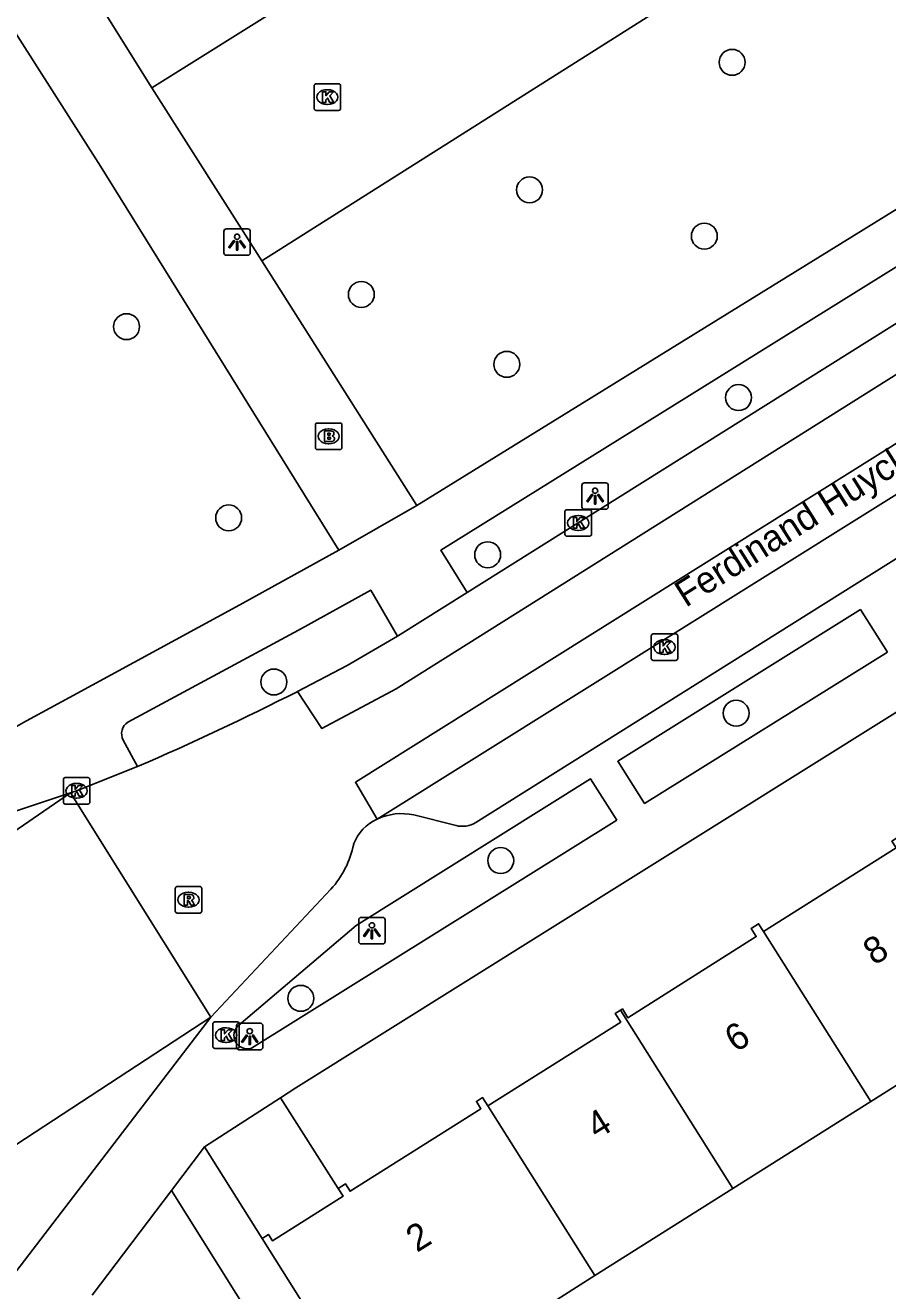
# Model space of a CAD drawing. Extents: x 160077 to 160945, y 386481 to 387498.
# Drawn here: x 160409.7 to 160442.23, y 386860.35 to 386908.06 of the extents above; entities that cross this region are included whole.
import ezdxf

# ---------------------------------------------------------------- set-up
doc = ezdxf.new("R2010")
doc.units = 0
for name, color, linetype in [('IMGEO_Boom', 7, 'Continuous'), ('IMGEO_Brandkraan', 7, 'Continuous'), ('IMGEO_Fietspad_gesloten', 7, 'Continuous'), ('IMGEO_Groenvoorziening', 7, 'Continuous'), ('IMGEO_Kolk', 7, 'Continuous'), ('IMGEO_Lichtpunt', 7, 'Continuous'), ('IMGEO_Openbare_ruimte_label', 7, 'Continuous'), ('IMGEO_Pand', 7, 'Continuous'), ('IMGEO_Pand_nummerreeks', 7, 'Continuous'), ('IMGEO_Rijbaan_lokaal_gesloten', 7, 'Continuous'), ('IMGEO_Rijbaan_lokaal_open', 7, 'Continuous'), ('IMGEO_Rioolput', 7, 'Continuous'), ('IMGEO_Voetpad_open', 7, 'Continuous')]:
    doc.layers.add(name, color=color, linetype=linetype)

msp = doc.modelspace()

# ---------------------------------------------------------------- linework, layer by layer
at = {"layer": 'IMGEO_Boom'}
for centre in [(160436.359, 386906.663), (160428.721, 386901.854), (160435.311, 386900.11), (160422.376, 386897.911), (160413.525, 386896.698), (160427.863, 386895.276), (160436.602, 386894.023), (160417.375, 386889.487), (160427.141, 386888.098), (160419.081, 386883.301), (160436.512, 386882.124), (160427.633, 386876.567), (160420.093, 386871.374)]:
    msp.add_circle(centre, 0.489, dxfattribs=at)
at = {"layer": 'IMGEO_Brandkraan'}
for p, q in [((160420.644, 386892.138), (160420.644, 386892.99)), ((160420.719, 386893.064), (160421.571, 386893.064)), ((160421.132, 386892.844), (160421.157, 386892.844)), ((160421.645, 386892.99), (160421.645, 386892.138)), ((160421.571, 386892.064), (160420.719, 386892.064)), ((160421.155, 386892.284), (160421.13, 386892.284))]:
    msp.add_line(p, q, dxfattribs=at)
for points in [[(160420.644, 386892.138), (160420.644, 386892.99)], [(160420.719, 386893.064), (160421.571, 386893.064)], [(160421.645, 386892.99), (160421.645, 386892.138)], [(160420.992, 386892.764), (160420.992, 386892.364), (160421.205, 386892.364)], [(160421.223, 386892.764), (160420.992, 386892.764)], [(160421.171, 386892.683), (160421.117, 386892.683), (160421.117, 386892.607)], [(160421.117, 386892.607), (160421.17, 386892.607)], [(160421.179, 386892.531), (160421.117, 386892.531), (160421.117, 386892.45)], [(160421.117, 386892.45), (160421.179, 386892.45)], [(160421.571, 386892.064), (160420.719, 386892.064)]]:
    msp.add_lwpolyline(points, dxfattribs=at)
for centre, radius, start, end in [((160420.721, 386892.988), 0.0765, 91.552, 178.448), ((160420.721, 386892.988), 0.0765, 91.552, 178.448), ((160421.569, 386892.988), 0.0765, 1.552, 88.448), ((160421.569, 386892.988), 0.0765, 1.552, 88.448), ((160421.172, 386892.645), 0.0379, 267.8285, 90.9355), ((160421.18, 386892.49), 0.0404, 269.8759, 90.5077), ((160421.211, 386892.615), 0.251, 268.6676, 293.5347), ((160421.227, 386892.619), 0.145, 59.4692, 91.5367), ((160421.252, 386892.666), 0.0922, 285.5137, 58.1501), ((160421.257, 386892.474), 0.105, 301.3115, 78.989), ((160420.721, 386892.14), 0.0765, 181.552, 268.448), ((160420.721, 386892.14), 0.0765, 181.552, 268.448), ((160421.569, 386892.14), 0.0765, 271.552, 358.448), ((160421.569, 386892.14), 0.0765, 271.552, 358.448)]:
    msp.add_arc(centre, radius, start, end, dxfattribs=at)
for centre, major_axis, ratio, start_param, end_param in [((160421.131, 386892.564), (-0.387, 0.002), 0.722429, 4.712389, 7.853982), ((160421.156, 386892.564), (-0.39, 0.002), 0.717154, 1.570796, 4.712389)]:
    msp.add_ellipse(centre, major_axis=major_axis, ratio=ratio, start_param=start_param, end_param=end_param, dxfattribs=at)
at = {"layer": 'IMGEO_Fietspad_gesloten'}
for points in [[(160408.572, 386878.179), (160411.413, 386879.123)], [(160416.702, 386870.665), (160416.575, 386870.496), (160409.222, 386860.905), (160408.542, 386860.066), (160407.918, 386859.274), (160407.31, 386858.499), (160403.74, 386853.668)]]:
    msp.add_lwpolyline(points, dxfattribs=at)
at = {"layer": 'IMGEO_Groenvoorziening'}
msp.add_lwpolyline([(160419.331, 386867.627), (160421.508, 386864.204)], dxfattribs=at)
at = {"layer": 'IMGEO_Kolk'}
for p, q in [((160420.595, 386904.926), (160420.595, 386905.778)), ((160420.67, 386905.852), (160421.522, 386905.852)), ((160421.596, 386905.778), (160421.596, 386904.926)), ((160421.083, 386905.632), (160421.108, 386905.632)), ((160421.522, 386904.852), (160420.67, 386904.852)), ((160421.106, 386905.072), (160421.081, 386905.072)), ((160430.056, 386888.871), (160430.056, 386889.723)), ((160430.131, 386889.797), (160430.983, 386889.797)), ((160430.544, 386889.577), (160430.569, 386889.577)), ((160431.057, 386889.723), (160431.057, 386888.871)), ((160430.567, 386889.017), (160430.542, 386889.017)), ((160430.983, 386888.797), (160430.131, 386888.797)), ((160433.311, 386884.189), (160433.311, 386885.041)), ((160433.386, 386885.115), (160434.238, 386885.115)), ((160433.799, 386884.895), (160433.824, 386884.895)), ((160434.312, 386885.041), (160434.312, 386884.189)), ((160433.822, 386884.335), (160433.797, 386884.335)), ((160434.238, 386884.115), (160433.386, 386884.115)), ((160411.139, 386878.773), (160411.139, 386879.625)), ((160411.214, 386879.699), (160412.066, 386879.699)), ((160411.627, 386879.479), (160411.652, 386879.479)), ((160412.14, 386879.625), (160412.14, 386878.773)), ((160412.066, 386878.699), (160411.214, 386878.699)), ((160411.65, 386878.919), (160411.625, 386878.919)), ((160416.775, 386869.56), (160416.775, 386870.412)), ((160416.85, 386870.486), (160417.702, 386870.486)), ((160417.776, 386870.412), (160417.776, 386869.56)), ((160417.263, 386870.266), (160417.288, 386870.266)), ((160417.702, 386869.486), (160416.85, 386869.486)), ((160417.286, 386869.706), (160417.261, 386869.706))]:
    msp.add_line(p, q, dxfattribs=at)
for points in [[(160420.595, 386904.926), (160420.595, 386905.778)], [(160420.67, 386905.852), (160421.522, 386905.852)], [(160421.596, 386905.778), (160421.596, 386904.926)], [(160420.916, 386905.552), (160421.039, 386905.552), (160421.039, 386905.401), (160421.169, 386905.552), (160421.333, 386905.552), (160421.187, 386905.401), (160421.34, 386905.152), (160421.188, 386905.152), (160421.103, 386905.316), (160421.039, 386905.249), (160421.039, 386905.152), (160420.916, 386905.152), (160420.916, 386905.552)], [(160421.522, 386904.852), (160420.67, 386904.852)], [(160430.056, 386888.871), (160430.056, 386889.723)], [(160430.131, 386889.797), (160430.983, 386889.797)], [(160430.377, 386889.497), (160430.5, 386889.497), (160430.5, 386889.346), (160430.63, 386889.497), (160430.794, 386889.497), (160430.648, 386889.346), (160430.801, 386889.097), (160430.649, 386889.097), (160430.564, 386889.261), (160430.5, 386889.194), (160430.5, 386889.097), (160430.377, 386889.097), (160430.377, 386889.497)], [(160431.057, 386889.723), (160431.057, 386888.871)], [(160430.983, 386888.797), (160430.131, 386888.797)], [(160433.311, 386884.189), (160433.311, 386885.041)], [(160433.386, 386885.115), (160434.238, 386885.115)], [(160433.632, 386884.815), (160433.755, 386884.815), (160433.755, 386884.664), (160433.885, 386884.815), (160434.049, 386884.815), (160433.903, 386884.664), (160434.056, 386884.415), (160433.904, 386884.415), (160433.819, 386884.579), (160433.755, 386884.512), (160433.755, 386884.415), (160433.632, 386884.415), (160433.632, 386884.815)], [(160434.312, 386885.041), (160434.312, 386884.189)], [(160434.238, 386884.115), (160433.386, 386884.115)], [(160411.139, 386878.773), (160411.139, 386879.625)], [(160411.214, 386879.699), (160412.066, 386879.699)], [(160412.14, 386879.625), (160412.14, 386878.773)], [(160411.46, 386879.399), (160411.583, 386879.399), (160411.583, 386879.248), (160411.713, 386879.399), (160411.877, 386879.399), (160411.731, 386879.248), (160411.884, 386878.999), (160411.732, 386878.999), (160411.647, 386879.163), (160411.583, 386879.096), (160411.583, 386878.999), (160411.46, 386878.999), (160411.46, 386879.399)], [(160412.066, 386878.699), (160411.214, 386878.699)], [(160416.775, 386869.56), (160416.775, 386870.412)], [(160416.85, 386870.486), (160417.702, 386870.486)], [(160417.776, 386870.412), (160417.776, 386869.56)], [(160417.096, 386870.186), (160417.219, 386870.186), (160417.219, 386870.035), (160417.349, 386870.186), (160417.513, 386870.186), (160417.367, 386870.035), (160417.52, 386869.786), (160417.368, 386869.786), (160417.283, 386869.95), (160417.219, 386869.883), (160417.219, 386869.786), (160417.096, 386869.786), (160417.096, 386870.186)], [(160417.702, 386869.486), (160416.85, 386869.486)]]:
    msp.add_lwpolyline(points, dxfattribs=at)
for centre, start, end in [((160420.672, 386905.776), 91.552, 178.448), ((160420.672, 386905.776), 91.552, 178.448), ((160421.52, 386905.776), 1.552, 88.448), ((160421.52, 386905.776), 1.552, 88.448), ((160420.672, 386904.928), 181.552, 268.448), ((160420.672, 386904.928), 181.552, 268.448), ((160421.52, 386904.928), 271.552, 358.448), ((160421.52, 386904.928), 271.552, 358.448), ((160430.133, 386889.721), 91.552, 178.448), ((160430.133, 386889.721), 91.552, 178.448), ((160430.981, 386889.721), 1.552, 88.448), ((160430.981, 386889.721), 1.552, 88.448), ((160430.133, 386888.873), 181.552, 268.448), ((160430.133, 386888.873), 181.552, 268.448), ((160430.981, 386888.873), 271.552, 358.448), ((160430.981, 386888.873), 271.552, 358.448), ((160433.388, 386885.039), 91.552, 178.448), ((160433.388, 386885.039), 91.552, 178.448), ((160434.236, 386885.039), 1.552, 88.448), ((160434.236, 386885.039), 1.552, 88.448), ((160433.388, 386884.191), 181.552, 268.448), ((160433.388, 386884.191), 181.552, 268.448), ((160434.236, 386884.191), 271.552, 358.448), ((160434.236, 386884.191), 271.552, 358.448), ((160411.216, 386879.623), 91.552, 178.448), ((160411.216, 386879.623), 91.552, 178.448), ((160412.064, 386879.623), 1.552, 88.448), ((160412.064, 386879.623), 1.552, 88.448), ((160411.216, 386878.775), 181.552, 268.448), ((160411.216, 386878.775), 181.552, 268.448), ((160412.064, 386878.775), 271.552, 358.448), ((160412.064, 386878.775), 271.552, 358.448), ((160416.852, 386870.41), 91.552, 178.448), ((160416.852, 386870.41), 91.552, 178.448), ((160417.7, 386870.41), 1.552, 88.448), ((160417.7, 386870.41), 1.552, 88.448), ((160416.852, 386869.562), 181.552, 268.448), ((160416.852, 386869.562), 181.552, 268.448), ((160417.7, 386869.562), 271.552, 358.448), ((160417.7, 386869.562), 271.552, 358.448)]:
    msp.add_arc(centre, 0.0765, start, end, dxfattribs=at)
for centre, major_axis, ratio, start_param, end_param in [((160421.082, 386905.352), (-0.387, 0.002), 0.722429, 4.712389, 7.853982), ((160421.107, 386905.352), (-0.39, 0.002), 0.717154, 1.570796, 4.712389), ((160430.543, 386889.297), (-0.387, 0.002), 0.722429, 4.712389, 7.853982), ((160430.568, 386889.297), (-0.39, 0.002), 0.717154, 1.570796, 4.712389), ((160433.798, 386884.615), (-0.387, 0.002), 0.722429, 4.712389, 7.853982), ((160433.823, 386884.615), (-0.39, 0.002), 0.717154, 1.570796, 4.712389), ((160411.626, 386879.199), (-0.387, 0.002), 0.722429, 4.712389, 7.853982), ((160411.651, 386879.199), (-0.39, 0.002), 0.717154, 1.570796, 4.712389), ((160417.262, 386869.986), (-0.387, 0.002), 0.722429, 4.712389, 7.853982), ((160417.287, 386869.986), (-0.39, 0.002), 0.717154, 1.570796, 4.712389)]:
    msp.add_ellipse(centre, major_axis=major_axis, ratio=ratio, start_param=start_param, end_param=end_param, dxfattribs=at)
at = {"layer": 'IMGEO_Lichtpunt'}
for p, q in [((160417.193, 386900.289), (160417.193, 386899.482)), ((160417.193, 386900.289), (160417.193, 386899.482)), ((160418.095, 386900.384), (160417.287, 386900.384)), ((160418.095, 386900.384), (160417.287, 386900.384)), ((160418.189, 386899.482), (160418.189, 386900.289)), ((160418.189, 386899.482), (160418.189, 386900.289)), ((160417.287, 386899.388), (160418.095, 386899.388)), ((160417.287, 386899.388), (160418.095, 386899.388)), ((160430.695, 386890.715), (160430.695, 386889.908)), ((160430.695, 386890.715), (160430.695, 386889.908)), ((160431.597, 386890.81), (160430.789, 386890.81)), ((160431.597, 386890.81), (160430.789, 386890.81)), ((160431.691, 386889.908), (160431.691, 386890.715)), ((160431.691, 386889.908), (160431.691, 386890.715)), ((160430.789, 386889.814), (160431.597, 386889.814)), ((160430.789, 386889.814), (160431.597, 386889.814)), ((160422.278, 386874.329), (160422.278, 386873.522)), ((160422.278, 386874.329), (160422.278, 386873.522)), ((160423.18, 386874.424), (160422.372, 386874.424)), ((160423.18, 386874.424), (160422.372, 386874.424)), ((160423.274, 386873.522), (160423.274, 386874.329)), ((160423.274, 386873.522), (160423.274, 386874.329)), ((160422.372, 386873.428), (160423.18, 386873.428)), ((160422.372, 386873.428), (160423.18, 386873.428)), ((160418.571, 386870.433), (160417.763, 386870.433)), ((160418.571, 386870.433), (160417.763, 386870.433)), ((160417.669, 386870.338), (160417.669, 386869.531)), ((160417.669, 386870.338), (160417.669, 386869.531)), ((160418.665, 386869.531), (160418.665, 386870.338)), ((160418.665, 386869.531), (160418.665, 386870.338)), ((160417.763, 386869.437), (160418.571, 386869.437)), ((160417.763, 386869.437), (160418.571, 386869.437))]:
    msp.add_line(p, q, dxfattribs=at)
for points in [[(160417.567, 386899.953), (160417.606, 386899.925), (160417.418, 386899.663), (160417.38, 386899.69), (160417.567, 386899.953)], [(160417.669, 386899.905), (160417.716, 386899.905), (160417.716, 386899.583), (160417.669, 386899.583), (160417.669, 386899.905)], [(160417.779, 386899.925), (160417.817, 386899.952), (160418.004, 386899.69), (160417.965, 386899.662), (160417.779, 386899.925)], [(160431.069, 386890.379), (160431.108, 386890.351), (160430.92, 386890.089), (160430.882, 386890.116), (160431.069, 386890.379)], [(160431.171, 386890.331), (160431.218, 386890.331), (160431.218, 386890.009), (160431.171, 386890.009), (160431.171, 386890.331)], [(160431.281, 386890.351), (160431.319, 386890.378), (160431.506, 386890.116), (160431.467, 386890.088), (160431.281, 386890.351)], [(160422.652, 386873.993), (160422.691, 386873.965), (160422.503, 386873.703), (160422.465, 386873.73), (160422.652, 386873.993)], [(160422.754, 386873.945), (160422.801, 386873.945), (160422.801, 386873.623), (160422.754, 386873.623), (160422.754, 386873.945)], [(160422.864, 386873.965), (160422.902, 386873.992), (160423.089, 386873.73), (160423.05, 386873.702), (160422.864, 386873.965)], [(160418.043, 386870.002), (160418.082, 386869.974), (160417.894, 386869.712), (160417.856, 386869.739), (160418.043, 386870.002)], [(160418.145, 386869.954), (160418.192, 386869.954), (160418.192, 386869.632), (160418.145, 386869.632), (160418.145, 386869.954)], [(160418.255, 386869.974), (160418.293, 386870.001), (160418.48, 386869.739), (160418.441, 386869.711), (160418.255, 386869.974)]]:
    msp.add_lwpolyline(points, dxfattribs=at)
for centre in [(160417.692, 386900.087), (160431.194, 386890.513), (160422.777, 386874.127), (160418.168, 386870.136)]:
    msp.add_circle(centre, 0.0994, dxfattribs=at)
for centre, start, end in [((160417.287, 386900.289), 90, 180), ((160417.287, 386900.289), 90, 180), ((160418.095, 386900.289), 0, 90), ((160418.095, 386900.289), 0, 90), ((160417.287, 386899.482), 180, 270), ((160417.287, 386899.482), 180, 270), ((160418.095, 386899.482), 270, 0), ((160418.095, 386899.482), 270, 360), ((160430.789, 386890.715), 90, 180), ((160430.789, 386890.715), 90, 180), ((160431.597, 386890.715), 0, 90), ((160431.597, 386890.715), 0, 90), ((160430.789, 386889.908), 180, 270), ((160430.789, 386889.908), 180, 270), ((160431.597, 386889.908), 270, 0), ((160431.597, 386889.908), 270, 360), ((160422.372, 386874.329), 90, 180), ((160422.372, 386874.329), 90, 180), ((160423.18, 386874.329), 0, 90), ((160423.18, 386874.329), 0, 90), ((160422.372, 386873.522), 180, 270), ((160422.372, 386873.522), 180, 270), ((160423.18, 386873.522), 270, 0), ((160423.18, 386873.522), 270, 360), ((160417.763, 386870.338), 90, 180), ((160417.763, 386870.338), 90, 180), ((160418.571, 386870.338), 0, 90), ((160418.571, 386870.338), 0, 90), ((160417.763, 386869.531), 180, 270), ((160417.763, 386869.531), 180, 270), ((160418.571, 386869.531), 270, 0), ((160418.571, 386869.531), 270, 360)]:
    msp.add_arc(centre, 0.0946, start, end, dxfattribs=at)
at = {"layer": 'IMGEO_Pand'}
for points in [[(160437.543, 386873.893), (160442.548, 386877.05), (160442.388, 386877.304), (160442.592, 386877.433)], [(160432.147, 386870.927), (160432.223, 386870.974), (160432.43, 386870.642), (160437.271, 386873.702), (160437.08, 386874.008), (160437.359, 386874.184), (160437.543, 386873.893)], [(160437.543, 386873.893), (160441.594, 386867.488)], [(160427.149, 386867.317), (160432.16, 386870.477), (160431.953, 386870.806), (160432.147, 386870.927)], [(160436.391, 386864.204), (160432.147, 386870.927)], [(160446.465, 386870.563), (160441.594, 386867.488)], [(160421.508, 386864.204), (160421.78, 386864.376), (160421.953, 386864.101), (160426.888, 386867.213), (160426.715, 386867.487), (160426.949, 386867.634), (160427.149, 386867.317)], [(160431.189, 386860.92), (160427.149, 386867.317)], [(160441.594, 386867.488), (160436.391, 386864.204)], [(160421.508, 386864.204), (160421.69, 386863.915), (160419.026, 386862.235), (160418.875, 386862.476), (160418.632, 386862.323)], [(160436.391, 386864.204), (160431.189, 386860.92)], [(160422.839, 386855.651), (160418.632, 386862.323)], [(160431.189, 386860.92), (160429.346, 386859.754), (160427.069, 386858.318), (160422.839, 386855.651)]]:
    msp.add_lwpolyline(points, dxfattribs=at)
at = {"layer": 'IMGEO_Rijbaan_lokaal_gesloten'}
for points in [[(160419.976, 386882.948), (160420.887, 386881.55), (160423.695, 386883.049), (160454.149, 386902.178), (160498.016, 386929.634)], [(160499.173, 386927.789), (160470.277, 386909.673), (160422.153, 386879.524), (160422.979, 386878.128)], [(160498.541, 386925.423), (160471.132, 386908.242), (160422.979, 386878.128)], [(160453.275, 386903.561), (160447.876, 386900.154), (160430.557, 386889.297), (160426.372, 386886.679)], [(160423.735, 386885.033), (160426.372, 386886.679)], [(160419.976, 386882.948), (160421.837, 386883.922), (160423.735, 386885.033)], [(160399.68, 386871.062), (160411.413, 386879.123)], [(160416.702, 386870.665), (160411.413, 386879.123)], [(160404.134, 386862.447), (160416.702, 386870.665)]]:
    msp.add_lwpolyline(points, dxfattribs=at)
at = {"layer": 'IMGEO_Rijbaan_lokaal_open'}
for points in [[(160418.626, 386899.176), (160445.701, 386916.313)], [(160416.321, 386914.248), (160419.644, 386908.926), (160414.476, 386905.699)], [(160414.476, 386905.699), (160418.626, 386899.176)], [(160411.413, 386879.123), (160411.64, 386879.199), (160413.94, 386880.112)], [(160416.702, 386870.665), (160421.228, 386875.484)]]:
    msp.add_lwpolyline(points, dxfattribs=at)
for centre, radius, start, end in [((160369.624, 386982.274), 111.36, 293.45046, 296.88228), ((160423.627, 386876.624), 1.638, 113.3148, 159.994), ((160418.55, 386877.906), 3.611, 317.8708, 348.4611)]:
    msp.add_arc(centre, radius, start, end, dxfattribs=at)
at = {"layer": 'IMGEO_Rioolput'}
for p, q in [((160415.36, 386874.665), (160415.36, 386875.517)), ((160415.435, 386875.591), (160416.287, 386875.591)), ((160415.848, 386875.371), (160415.873, 386875.371)), ((160416.361, 386875.517), (160416.361, 386874.665)), ((160415.871, 386874.811), (160415.846, 386874.811)), ((160416.287, 386874.591), (160415.435, 386874.591))]:
    msp.add_line(p, q, dxfattribs=at)
for points in [[(160415.36, 386874.665), (160415.36, 386875.517)], [(160415.435, 386875.591), (160416.287, 386875.591)], [(160415.949, 386875.289), (160415.697, 386875.291), (160415.697, 386874.891)], [(160415.875, 386875.21), (160415.821, 386875.21), (160415.821, 386875.129)], [(160416.361, 386875.517), (160416.361, 386874.665)], [(160415.697, 386874.891), (160415.821, 386874.891), (160415.821, 386875.053), (160415.832, 386875.053)], [(160415.821, 386875.129), (160415.873, 386875.129)], [(160415.879, 386875.024), (160415.95, 386874.891), (160416.09, 386874.891), (160416.025, 386875.017)], [(160416.287, 386874.591), (160415.435, 386874.591)]]:
    msp.add_lwpolyline(points, dxfattribs=at)
for centre, radius, start, end in [((160415.437, 386875.515), 0.0765, 91.552, 178.448), ((160415.437, 386875.515), 0.0765, 91.552, 178.448), ((160415.881, 386875.114), 0.0964, 77.0061, 93.1865), ((160415.895, 386875.171), 0.0378, 276.6634, 79.6772), ((160415.948, 386875.179), 0.109, 350.3612, 89.416), ((160415.946, 386875.179), 0.112, 277.5842, 350.9817), ((160416.285, 386875.515), 0.0765, 1.552, 88.448), ((160416.285, 386875.515), 0.0765, 1.552, 88.448), ((160415.831, 386875), 0.0533, 26.0293, 88.6989), ((160415.857, 386875.318), 0.19, 274.7715, 282.9687), ((160415.93, 386874.964), 0.108, 29.5134, 73.7905), ((160415.437, 386874.667), 0.0765, 181.552, 268.448), ((160415.437, 386874.667), 0.0765, 181.552, 268.448), ((160416.285, 386874.667), 0.0765, 271.552, 358.448), ((160416.285, 386874.667), 0.0765, 271.552, 358.448)]:
    msp.add_arc(centre, radius, start, end, dxfattribs=at)
for centre, major_axis, ratio, start_param, end_param in [((160415.847, 386875.091), (-0.387, 0.002), 0.722429, 4.712389, 7.853982), ((160415.872, 386875.091), (-0.39, 0.002), 0.717154, 1.570796, 4.712389)]:
    msp.add_ellipse(centre, major_axis=major_axis, ratio=ratio, start_param=start_param, end_param=end_param, dxfattribs=at)
at = {"layer": 'IMGEO_Voetpad_open'}
for points in [[(160387.823, 386942.091), (160389.939, 386938.794), (160392.284, 386934.918), (160394.729, 386930.878), (160396.796, 386927.687), (160399.533, 386923.281), (160403.038, 386917.636), (160408.864, 386908.506), (160412.535, 386902.752), (160416.406, 386896.516), (160421.525, 386888.269)], [(160426.691, 386878.004), (160472.2, 386906.553), (160496.977, 386922.083)], [(160503.979, 386920.59), (160500, 386918.098), (160419.904, 386867.997), (160419.331, 386867.627)], [(160414.476, 386905.699), (160411.153, 386911.02)], [(160450.017, 386905.729), (160424.466, 386889.949)], [(160426.372, 386886.679), (160425.369, 386888.267), (160452.383, 386905.061), (160453.275, 386903.561)], [(160424.466, 386889.949), (160418.626, 386899.176)], [(160424.466, 386889.949), (160421.525, 386888.269)], [(160421.525, 386888.269), (160417.798, 386886.204), (160411.377, 386882.716), (160409.893, 386881.917)], [(160413.576, 386881.791), (160420.003, 386885.249), (160422.733, 386886.769), (160423.735, 386885.033)], [(160442.215, 386884.428), (160441.198, 386886.032), (160432.048, 386880.31), (160433.056, 386878.721), (160442.215, 386884.428)], [(160413.94, 386880.112), (160413.4, 386881.105)], [(160432.012, 386878.087), (160431.019, 386879.651), (160422.186, 386874.126), (160417.76, 386870.362)], [(160418.233, 386869.493), (160432.012, 386878.087)], [(160424.352, 386878.287), (160425.949, 386877.889)], [(160416.466, 386865.776), (160419.331, 386867.627)], [(160416.466, 386865.776), (160415.215, 386864.126)], [(160418.632, 386862.323), (160416.466, 386865.776)], [(160415.215, 386864.126), (160412.23, 386860.189)], [(160423.252, 386842.489), (160427.229, 386844.983), (160415.215, 386864.126)]]:
    msp.add_lwpolyline(points, dxfattribs=at)
for centre, radius, start, end in [((160400.977, 386897.211), 17.703, 284.731, 300.2393), ((160413.851, 386881.355), 0.515, 122.2065, 209.0146), ((160423.89, 386876.27), 2.069, 77.0918, 116.1196), ((160426.186, 386878.809), 0.95, 255.5424, 302.0775), ((160418.076, 386869.971), 0.503, 128.8792, 288.24)]:
    msp.add_arc(centre, radius, start, end, dxfattribs=at)

# ---------------------------------------------------------------- texts
at = {"layer": 'IMGEO_Openbare_ruimte_label'}
msp.add_text('Ferdinand Huyckstraat', height=1, rotation=32.2604, dxfattribs=at).set_placement((160434.612, 386886.093))
at = {"layer": 'IMGEO_Pand_nummerreeks'}
for s, rotation, p in [('8', 32.1429, (160441.714, 386872.594)), ('6', 32.1429, (160436.492, 386869.313)), ('4', 32.1406, (160431.272, 386866.034)), ('2', 32.0374, (160424.472, 386861.773))]:
    msp.add_text(s, height=1, rotation=rotation, dxfattribs=at).set_placement(p)

doc.saveas('drawing.dxf')
